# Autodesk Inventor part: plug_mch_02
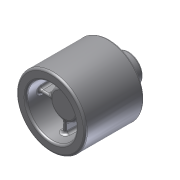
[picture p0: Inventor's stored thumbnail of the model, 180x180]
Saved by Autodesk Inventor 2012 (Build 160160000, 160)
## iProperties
Shininess: 64.0
Length Units: 11269
Angle Units: 11279
Time Units: 11290
Mass Units: 11283
Length Display Precision: 3
Angle Display Precision: 2
Company: Autodesk
Created: 2002-07
Part Number: plug_mch_02
Document SubType Name: Modeling
Designer: Lieven Grauls
Stock Number: plug_mch_02
Project: Valve Techcamp 2008
Density: 1 g/cm^3
Material: Default
Density: 0.0
Volumn: 0.0
Area: 0.0
PropertySet Name: Model Information
Control State: 0
Master: False
Checked Out: False
Author: Lieven Grauls
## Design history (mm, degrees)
node "plug_cast_02" dims "d1" = 10
sketch "Sketch6"
  geometry: L1 (-25, 45)-(25, 45) reference; L2 (26.5, 43.5)-(26.5, 1.5) reference; L3 (25, 45)-(26.5, 45); L4 (26.5, 45)-(26.5, 43.5); L5 (25, 45)-(26.5, 43.5); L6 (0, -12)-(0, 72) reference; 1 further point
  constraints: 6 end point, 2 perpendicular
revolve "Revolution2" sketch "Sketch6" stored, may be unused: angle "d47" = 90 deg
node "Volumenkörper1"
node "Volumenkörpern"
node "Oberflächenkörpern"
tag "Bezeichnung2"
feature "Volumenkörper1::plug_cast_02" dims "d1" = 10
other parameters: "d2" = 50.65
